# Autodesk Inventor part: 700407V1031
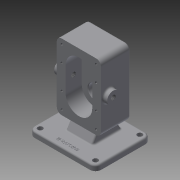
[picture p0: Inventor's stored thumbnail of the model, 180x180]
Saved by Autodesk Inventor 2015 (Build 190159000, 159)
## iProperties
Created: 2020-04
Part Number: 700407V1031
Material: 일반
Document SubType Name: Modeling
Designer: now
Density: 1 g/cm^3
Appearance: 기본값
Author: now
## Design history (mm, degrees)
sketch "스케치1"
  geometry: L1 (40, -60)-(-40, -60); L2 (-40, -60)-(-40, 60); L3 (-40, 60)-(40, 60); L4 (40, 60)-(40, -60); L5 (40, -60)-(-40, 60); L6 (-40, -60)-(40, 60); 1 further point
  constraints: 12 end point, 2 midpoint, 2 parallel, 1 horizontal, 1 perpendicular
  dimensions: "d0" = 80 distance of L2.end L3.end; "d1" = 120 distance of L3.end L1.start
extrude "돌출1" new body sketch "스케치1" distance "d2" = 53; taper "d3" = 0 deg
sketch "스케치2"
  geometry: L1 (0, -22)-(0, 22); L2 (-24, -22)-(-24, 22); L3 (24, 22)-(24, -22); A1 r 24 centre (0, -22) between (-24, -22) and (24, -22); A2 r 24 centre (0, 22) between (24, 22) and (-24, 22); 1 further point
  constraints: 8 end point, 4 point on circle, 4 tangent, 2 centre point, 1 midpoint, 1 parallel, 1 vertical
  dimensions: "d4" = 24 radius of A2; "d5" = 44 distance of L1.start L1.end
extrude "돌출2" cut sketch "스케치2" distance "d6" = 29; taper "d7" = 0 deg
sketch "스케치3"
  geometry: C1 r 19 at (0, -22); 1 further point
  constraints: 1 centre point, 1 vertical alignment
  dimensions: "d8" = 38 diameter of C1; "d9" = 22 distance of point (0, 0) C1.centre
extrude "돌출3" join sketch "스케치3" distance "d10" = 17; taper "d11" = 0 deg
sketch "스케치4"
  geometry: C1 r 19 at (0, 0) reference; 1 further point
hole "구멍1" sketch "스케치4" at (0, 0) diameter "d12" = 17; stored, may be unused: countersink angle "d16" = 90 deg, drill point angle "d18" = 118 deg; dims "d13" = 6, "d14" = 28, "d15" = 7.3, "d17" = 8
sketch "스케치5"
  geometry: C1 r 12.5 at (0, 22); A1 r 24 centre (0, 22) between (24, 22) and (-24, 22) reference; 1 further point
  constraints: 1 centre point, 1 coincident
  dimensions: "d19" = 25 diameter of C1
extrude "돌출4" cut sketch "스케치5" distance "d20" = 15; taper "d21" = 0 deg
sketch "스케치6"
  geometry: C1 r 12.5 at (0, -22); A1 r 24 centre (0, -22) between (-24, -22) and (24, -22) reference; 1 further point
  constraints: 1 centre point, 1 coincident
  dimensions: "d22" = 25 diameter of C1
extrude "돌출5" cut sketch "스케치6" distance "d23" = 15; taper "d24" = 0 deg
node "작업 평면1"
node "작업 평면2"
sketch "스케치7"
  geometry: L1 (100, -30)-(-20, -30); L2 (-20, -30)-(-20, 70); L3 (-20, 70)-(100, 70); L4 (100, 70)-(100, -30); L5 (100, -30)-(-20, 70); L6 (-20, -30)-(100, 70); L7 (59, 70)-(21, 70) reference; 3 further points
  constraints: 12 end point, 3 midpoint, 2 parallel, 1 horizontal, 1 horizontal alignment, 1 perpendicular, 1 vertical alignment
  dimensions: "d26" = 120 distance between parallel lines of L4 L2; "d27" = 100 distance of L1.end L2.end
extrude "돌출6" join sketch "스케치7" distance "d29" = 10; taper "d30" = 0 deg
sketch "스케치8"
  geometry: L1 (100, 70)-(-20, 70) reference; L2 (64, 0)-(16, 0); L3 (16, 0)-(16, 53); L4 (16, 53)-(64, 53); L5 (64, 53)-(64, 0); L6 (64, 0)-(16, 53); L7 (16, 0)-(64, 53); 3 further points
  constraints: 12 end point, 3 midpoint, 2 parallel, 1 horizontal, 1 perpendicular, 1 vertical alignment
  dimensions: "d31" = 48 distance of L3.end L4.end; "d32" = 53 distance of L2.end L3.end; "d33" = 17 distance between parallel lines of L4 L1
extrude "돌출7" new body sketch "스케치8" distance "d34" = 30; taper "d35" = 0 deg
feature "면 기울기1" dims angle "d36" = 30 deg
feature "결합1"
  node "솔리드2"
sketch "스케치9"
  geometry: L1 (150, 70)-(150, -30) reference; C1 r 11 at (60, 14); 1 further point
  constraints: 1 centre point
  dimensions: "d37" = 22 diameter of C1; "d38" = 90 distance from line of L1 C1.centre; "d39" = 14 distance of C1.centre point (60, 0)
extrude "돌출8" join sketch "스케치9" distance "d40" = 8; taper "d41" = 0 deg
sketch "스케치10"
  geometry: C1 r 11 at (0, 0) reference; 1 further point
hole "구멍2" sketch "스케치10" at (0, 0) diameter "d42" = 8.376; stored, may be unused: countersink angle "d46" = 90 deg, drill point angle "d48" = 118 deg; dims "d43" = 20, "d44" = 28, "d45" = 7.3, "d47" = 27.3
fillet "모깎기1" dims "d49" = 3
fillet "모깎기2" dims "d50" = 9
sketch "스케치11"
  geometry: A1 r 9 centre (-31, -51) between (-40, -51) and (-31, -60) reference; A2 r 9 centre (31, -51) between (31, -60) and (40, -51) reference; A3 r 9 centre (31, 51) between (40, 51) and (31, 60) reference; A4 r 9 centre (-31, 51) between (-31, 60) and (-40, 51) reference; 1 further point
hole "구멍3" sketch "스케치11" at (-31, 51), (31, 51), (-31, -51), (31, -51) diameter "d51" = 4.134; stored, may be unused: countersink angle "d55" = 90 deg, drill point angle "d57" = 118 deg; dims "d52" = 10, "d53" = 28, "d54" = 7.3, "d56" = 12
sketch "스케치12"
  geometry: C1 r 2.067 at (-31, 51) reference; C2 r 2.067 at (31, 51) reference; 5 further points
  constraints: 4 vertical alignment
  dimensions: "d58" = 44 distance of point (-31, -22) point (-31, 22); "d59" = 22 vertical distance of point (-31, 22) point (0, 0); "d60" = 44 distance of point (31, -22) point (31, 22); "d61" = 22 vertical distance of point (31, -22) point (0, 0)
hole "구멍4" sketch "스케치12" at (-31, 22), (-31, -22), (31, 22), (31, -22) diameter "d62" = 4.134; stored, may be unused: countersink angle "d66" = 90 deg, drill point angle "d68" = 118 deg; dims "d63" = 10, "d64" = 28, "d65" = 7.3, "d67" = 12
chamfer "모따기1" distance "d69" = 0.7; stored, may be unused: second distance "d70" = 2, angle "d71" = 30 deg
fillet "모깎기3" dims "d72" = 0.5
chamfer "모따기2" distance "d73" = 1; stored, may be unused: second distance "d74" = 2, angle "d75" = 30 deg
fillet "모깎기4" dims "d76" = 10
sketch "스케치13"
  geometry: A1 r 10 centre (-10, 60) between (-10, 70) and (-20, 60) reference; A2 r 10 centre (-10, -20) between (-20, -20) and (-10, -30) reference; A3 r 10 centre (90, -20) between (90, -30) and (100, -20) reference; A4 r 10 centre (90, 60) between (100, 60) and (90, 70) reference; 1 further point
hole "구멍5" sketch "스케치13" at (-10, -20), (-10, 60), (90, -20), (90, 60) diameter "d77" = 9; stored, may be unused: countersink angle "d81" = 90 deg, drill point angle "d83" = 118 deg; dims "d78" = 6, "d79" = 4, "d80" = 2, "d82" = 8
fillet "모깎기5" dims "d84" = 3
fillet "모깎기6" dims "d85" = 3
fillet "모깎기7" dims "d86" = 3
fillet "모깎기8" dims "d87" = 3
fillet "모깎기9" dims "d88" = 3
sketch "스케치14"
  geometry: L1 (-10, -30)-(90, -30) reference; L2 (-20, 60)-(-20, -20) reference; 2 further points
  constraints: 1 other
  dimensions: "d89" = 10 distance from line of L1 point (40, -20); "d90" = 60 distance from line of point (40, -20) L2
feature "엠보싱1" sketch "스케치14" dims "d91" = 0.5, "d92" = 0
fillet "모깎기10" dims "d93" = 3
node "솔리드1"
mirror "대칭1"
